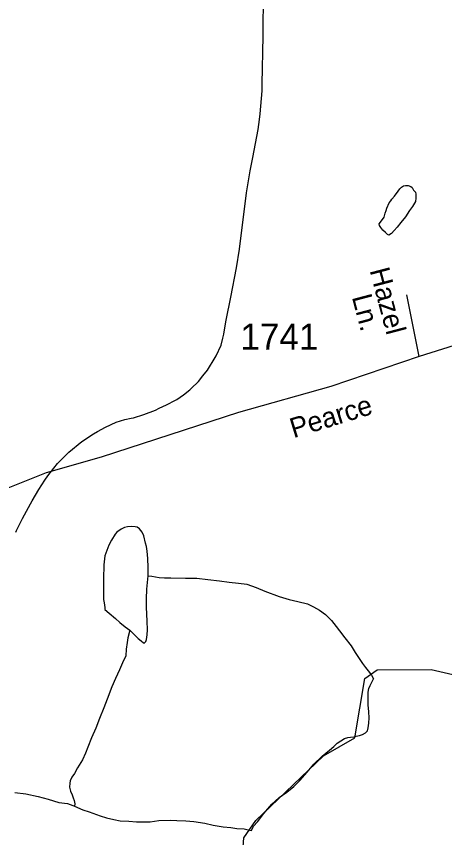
# Model space of a CAD drawing. Extents: x 2126262 to 2293712, y 749403 to 919119.
# Drawn here: x 2218920 to 2220963, y 782578 to 786501 of the extents above; entities that cross this region are included whole.
import ezdxf

# ---------------------------------------------------------------- set-up
doc = ezdxf.new("R2010")
doc.units = 0
for name, color, linetype in [('Exist Hydrographic Creek Single Shore', 7, 'Continuous'), ('Exist Hydrographic Misc Water Feature', 7, 'Continuous'), ('Exist Road Non-System Type 51', 7, 'Continuous'), ('Exist Road Non-System Type 51 Label', 7, 'Continuous'), ('Exist Road Secondary Type 51 Attributed', 7, 'Continuous'), ('Exist Road Secondary Type 51 Label', 7, 'Continuous'), ('Exist Road Secondary Type 51 Number Label', 7, 'Continuous')]:
    doc.layers.add(name, color=color, linetype=linetype)

msp = doc.modelspace()

# ---------------------------------------------------------------- linework, layer by layer
at = {"layer": 'Exist Hydrographic Creek Single Shore'}
for points in [[(2220063, 782660.7), (2220385.1, 782969), (2220535, 783054.5), (2220583, 783338.9), (2220641, 783380.3), (2220899, 783381.6), (2221099.1, 783334.9), (2221417, 783167.6), (2221858, 783188), (2222206.2, 783340.1)], [(2218216.1, 779799), (2218409, 779614.6), (2218542.9, 779559.4), (2218659, 779583.2), (2218784.1, 779669.3), (2218899.9, 779778.4), (2219240.1, 779938.7), (2219364, 780047.7), (2219413, 780154.9), (2219444.9, 780347.8), (2219360.1, 780664.4), (2219375, 780847.8), (2219424, 780971.4), (2219499.1, 781065), (2219790.1, 781124.6), (2219922.9, 781200.6), (2220036.9, 781450.9), (2220076.1, 781860.1), (2219958, 782042.9), (2219957, 782210.2), (2219982, 782252.4), (2220005, 782576.6), (2220063, 782660.7)]]:
    msp.add_lwpolyline(points, dxfattribs=at)
at = {"layer": 'Exist Hydrographic Misc Water Feature'}
for p, q in [((2219868.8, 784871.8), (2219872.3, 784878.8)), ((2219679, 784667.9), (2219684.5, 784671.6)), ((2219582.8, 784620.5), (2219601.7, 784629)), ((2219287.1, 784507.2), (2219306.6, 784518.1)), ((2218986.1, 784173), (2218994.3, 784187)), ((2218916, 784037.9), (2218919.9, 784045.9))]:
    msp.add_line(p, q, dxfattribs=at)
for points in [[(2220095.2, 786296.2), (2220100.1, 786732), (2220106.7, 787027.9)], [(2220095.2, 786296.2), (2220100.1, 786732), (2220106.7, 787027.9)], [(2220091.9, 786145.1), (2220095, 786286.3), (2220095.2, 786296.2)], [(2220080, 786008.2), (2220083.7, 786035.2), (2220091.9, 786145.1)], [(2220080, 786008.2), (2220083.7, 786035.2), (2220091.9, 786145.1)], [(2220048.1, 785827.1), (2220073.3, 785961.4), (2220080, 786008.2)], [(2220048.1, 785827.1), (2220073.3, 785961.4), (2220080, 786008.2)], [(2219942.7, 785159.7), (2219969.7, 785299.1), (2219984.1, 785389.5), (2220017.9, 785657.4), (2220036, 785762.4), (2220048.1, 785827.1)], [(2219942.7, 785159.7), (2219969.7, 785299.1), (2219984.1, 785389.5), (2220017.9, 785657.4), (2220036, 785762.4), (2220048.1, 785827.1)], [(2220698.1, 785610.3), (2220706.3, 785620.4), (2220712.2, 785628.4), (2220724.3, 785642.4), (2220741.9, 785666.5), (2220749.5, 785676.7), (2220757.7, 785684.8), (2220767.6, 785691), (2220777.2, 785692.8), (2220789.7, 785692.9), (2220801.8, 785689.1), (2220808, 785682.9), (2220815.8, 785671.2), (2220823.8, 785661), (2220826, 785651.4), (2220826, 785643.3), (2220826, 785633.1), (2220824.2, 785617.2), (2220810.4, 785592.9), (2220796.5, 785573.1), (2220777, 785542.7), (2220754.9, 785516.9), (2220737, 785494.8), (2220722.9, 785478.7), (2220709.6, 785464.5), (2220697.2, 785456.6), (2220691.1, 785458.4), (2220681.3, 785468.4), (2220669.4, 785480.3), (2220658.9, 785492), (2220653, 785501.8), (2220651.3, 785510.2), (2220663, 785523.9), (2220674.9, 785542.3), (2220680.4, 785560.2), (2220684.5, 785574.2), (2220688.2, 785584.5), (2220698.1, 785610.3)], [(2219915, 785013.5), (2219920.9, 785049.3), (2219942.7, 785159.7)], [(2219915, 785013.5), (2219920.9, 785049.3), (2219942.7, 785159.7)], [(2219905.1, 784963.8), (2219910.1, 784982.9), (2219915, 785013.5)], [(2219905.1, 784963.8), (2219910.1, 784982.9), (2219915, 785013.5)], [(2219872.3, 784878.8), (2219897.1, 784930.8), (2219905.1, 784963.8)], [(2219872.3, 784878.8), (2219897.1, 784930.8), (2219905.1, 784963.8)], [(2219809.2, 784783.2), (2219831.7, 784811.6), (2219868.8, 784871.8)], [(2219809.2, 784783.2), (2219831.7, 784811.6), (2219868.8, 784871.8)], [(2219747.9, 784717.8), (2219754, 784722.8), (2219788.3, 784757), (2219809.2, 784783.2)], [(2219747.9, 784717.8), (2219754, 784722.8), (2219788.3, 784757), (2219809.2, 784783.2)], [(2219684.5, 784671.6), (2219717.7, 784693.8), (2219747.9, 784717.8)], [(2219684.5, 784671.6), (2219717.7, 784693.8), (2219747.9, 784717.8)], [(2219601.7, 784629), (2219636.1, 784644.8), (2219679, 784667.9)], [(2219601.7, 784629), (2219636.1, 784644.8), (2219679, 784667.9)], [(2219467.3, 784581.1), (2219478, 784583.5), (2219527.8, 784599.5), (2219582.8, 784620.5)], [(2219467.3, 784581.1), (2219478, 784583.5), (2219527.8, 784599.5), (2219582.8, 784620.5)], [(2219306.6, 784518.1), (2219344.1, 784539.3), (2219396, 784563.1), (2219416.9, 784568.8)], [(2219306.6, 784518.1), (2219344.1, 784539.3), (2219396, 784563.1), (2219416.9, 784568.8)], [(2219416.9, 784568.8), (2219437.8, 784574.6), (2219467.3, 784581.1)], [(2219416.9, 784568.8), (2219437.8, 784574.6), (2219467.3, 784581.1)], [(2219080.2, 784320.1), (2219115.1, 784364.8), (2219169, 784419.4), (2219231.9, 784470.6), (2219287.1, 784507.2)], [(2219080.2, 784320.1), (2219115.1, 784364.8), (2219169, 784419.4), (2219231.9, 784470.6), (2219287.1, 784507.2)], [(2219055.6, 784285.6), (2219068.9, 784305.8), (2219080.2, 784320.1)], [(2219055.6, 784285.6), (2219068.9, 784305.8), (2219080.2, 784320.1)], [(2218994.3, 784187), (2219026.3, 784240.8), (2219055.6, 784285.6)], [(2218994.3, 784187), (2219026.3, 784240.8), (2219055.6, 784285.6)], [(2218919.9, 784045.9), (2218947.9, 784102.9), (2218986.1, 784173)], [(2218919.9, 784045.9), (2218947.9, 784102.9), (2218986.1, 784173)], [(2219548.8, 783829.2), (2219548.5, 783869), (2219546.3, 783911.1), (2219544.2, 783947.2), (2219539.7, 783968.9), (2219536, 783984.9), (2219527.6, 784019), (2219519.6, 784036.9), (2219507.3, 784052.5), (2219495.6, 784060.8), (2219485.6, 784062.7), (2219467.8, 784064.6), (2219449.5, 784062.5), (2219435.6, 784060.1), (2219419.8, 784052), (2219399.5, 784038), (2219391.5, 784027.8), (2219373.6, 783999.7), (2219360.3, 783975.7), (2219350.5, 783949.6), (2219342.3, 783923.7), (2219338.4, 783895.5), (2219336.5, 783881.6), (2219335.5, 783813.6), (2219335.7, 783781.5), (2219335.7, 783745.8), (2219335.7, 783715.8), (2219338.2, 783699.6), (2219342.3, 783677.9), (2219342.3, 783667.7), (2219362.2, 783649.7), (2219392.3, 783624.1), (2219412.6, 783606), (2219438.8, 783584.6), (2219460.8, 783568.7)], [(2219460.8, 783568.7), (2219501, 783528.9), (2219514.9, 783518.7), (2219525.4, 783509), (2219529.3, 783507.2), (2219533.4, 783511.1), (2219537.3, 783514.9), (2219541.2, 783524.9), (2219543, 783546.9), (2219544.9, 783571), (2219544.4, 783611.3), (2219539.9, 783679.2), (2219539.9, 783719), (2219541.6, 783765), (2219548.8, 783829.2)], [(2219548.8, 783829.2), (2219565.2, 783827.2), (2219601, 783821.3), (2219627.1, 783819.8), (2219656.8, 783819.8), (2219726.7, 783818.2), (2219780.9, 783816.9), (2219833.2, 783811), (2219889.1, 783805.4), (2219934.9, 783797.7), (2219979, 783793.9), (2220018.7, 783788.3), (2220063.4, 783772.6), (2220105.5, 783754.9), (2220173.5, 783729.6), (2220221.3, 783715.9), (2220263.6, 783706.3), (2220309.5, 783694.5), (2220337.8, 783680.5), (2220365.9, 783664.9), (2220394.2, 783643.2), (2220423.9, 783615.1), (2220446.5, 783587.4), (2220462.3, 783565.5), (2220486.5, 783531.8), (2220517.2, 783494), (2220536.9, 783462.2), (2220571.6, 783410.3), (2220585.3, 783390.4), (2220598, 783374.7), (2220613.8, 783354.8), (2220624, 783336.6)], [(2219460.8, 783568.7), (2219450.9, 783532.5), (2219447.5, 783510.7), (2219443.8, 783478.4), (2219441.7, 783446.6), (2219425.9, 783412.5), (2219412, 783380.1), (2219392.3, 783338.1), (2219374.7, 783298.1), (2219353.1, 783240.1), (2219337.5, 783197.9), (2219316, 783147.6), (2219298.2, 783101.6), (2219278.5, 783055.5), (2219260.7, 783009.5), (2219248.8, 782981.2), (2219235.4, 782949.2), (2219211.6, 782911), (2219197.5, 782885.1), (2219183.8, 782866.9), (2219176.2, 782849), (2219174.1, 782838.8), (2219173.7, 782818.9), (2219178.4, 782800.8), (2219186, 782783), (2219190.5, 782769), (2219194.6, 782755), (2219198.7, 782738.9), (2219196.7, 782729.1)], [(2220041.1, 782612.9), (2220050.9, 782632.9), (2220070.8, 782653), (2220100.3, 782693.2), (2220138.5, 782737.4), (2220174, 782769.7), (2220209.8, 782796), (2220243.9, 782822.1), (2220273.2, 782850.5), (2220307, 782890.8), (2220339, 782929), (2220378.4, 782967.2), (2220414.7, 782995.4), (2220434.2, 783013.6), (2220450, 783029.5), (2220486, 783052), (2220502, 783056.1), (2220513.9, 783058), (2220532, 783060.1), (2220541.8, 783062.3), (2220557.8, 783066.3), (2220571.6, 783070.3), (2220585.7, 783078.4), (2220596, 783088.6), (2220599.4, 783102.6), (2220601.5, 783124.7), (2220603.3, 783150.8), (2220601.1, 783178.6), (2220598.6, 783212.7), (2220598.8, 783236.6), (2220598.4, 783272.4), (2220602.3, 783290.4), (2220608.5, 783304.5), (2220618.1, 783324.5), (2220624, 783336.6)], [(2218912.3, 782793.1), (2218964.6, 782787.3), (2219022.6, 782774), (2219070.4, 782762.3), (2219122.7, 782746.3), (2219162.8, 782740.7), (2219188.9, 782731.1), (2219196.7, 782729.1)], [(2219196.7, 782729.1), (2219236.5, 782711.3), (2219266.8, 782701.4), (2219319.1, 782681.8), (2219349, 782672), (2219384.7, 782664.6), (2219415.3, 782658.7), (2219456.9, 782656.9), (2219493, 782653.1), (2219557.2, 782653.6), (2219599, 782659.8), (2219655, 782662.3), (2219684.9, 782660.6), (2219728.8, 782658.8), (2219766.9, 782655.1), (2219819.2, 782647.3), (2219859.2, 782637.6), (2219907.2, 782629.9), (2219943.1, 782626.1), (2219971, 782622.3), (2220007.2, 782620.9), (2220025.3, 782614.9), (2220041.1, 782612.9)]]:
    msp.add_lwpolyline(points, dxfattribs=at)
at = {"layer": 'Exist Road Non-System Type 51'}
msp.add_line((2220842.6, 784876.6), (2220782.6, 785171.4), dxfattribs=at)
at = {"layer": 'Exist Road Secondary Type 51 Attributed'}
msp.add_lwpolyline([(2223096.4, 787467.1), (2222999, 786953.8), (2222835.7, 786133.8), (2222777, 785952.2), (2222690.5, 785801.4), (2222550.9, 785656.1), (2222391.8, 785541.5), (2221737.3, 785190.9), (2221480.5, 785076.4), (2220842.6, 784876.6), (2220419.7, 784732.8), (2219980.1, 784608.4), (2219323.4, 784395.4), (2219061.1, 784320), (2218862.9, 784241.8), (2218642.4, 784144), (2217549.2, 783609), (2217328.8, 783514.9)], dxfattribs=at)

# ---------------------------------------------------------------- texts
at = {"layer": 'Exist Road Non-System Type 51 Label'}
for s, p in [('Hazel', (2220605, 785287.9)), ('Ln.', (2220520.4, 785160.7))]:
    msp.add_text(s, height=95, rotation=284.7887, dxfattribs=at).set_placement(p)
at = {"layer": 'Exist Road Secondary Type 51 Label'}
msp.add_text('Pearce', height=95, rotation=17.0926, dxfattribs=at).set_placement((2220242.2, 784485.6))
at = {"layer": 'Exist Road Secondary Type 51 Number Label'}
msp.add_text('1741', height=125, dxfattribs=at).set_placement((2219988.8, 784908.5))

doc.saveas('drawing.dxf')
